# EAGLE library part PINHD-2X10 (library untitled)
PIN HEADER
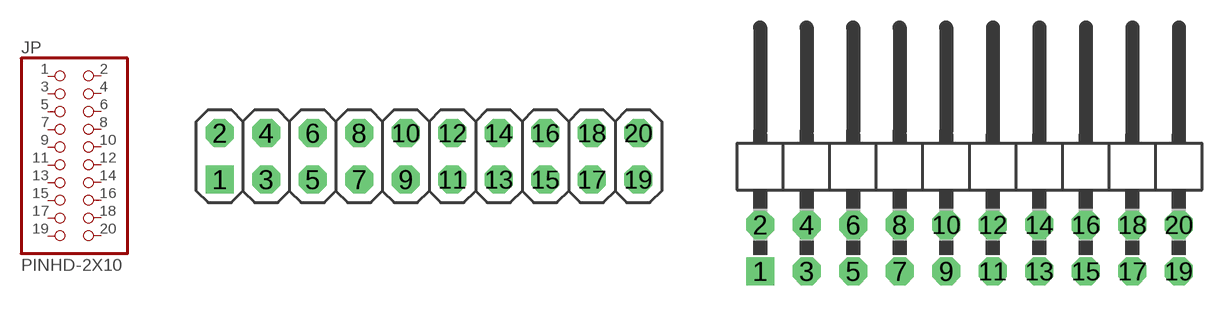
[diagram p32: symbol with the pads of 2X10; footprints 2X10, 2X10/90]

Designator prefix JP

## PINHD-2X10_2.54  [2X10]
1  1  pas
2  2  pas
3  3  pas
4  4  pas
5  5  pas
6  6  pas
7  7  pas
8  8  pas
9  9  pas
10  10  pas
11  11  pas
12  12  pas
13  13  pas
14  14  pas
15  15  pas
16  16  pas
17  17  pas
18  18  pas
19  19  pas
20  20  pas

## PINHD-2X10_2.54-90°  [2X10/90]
Pads as for 2X10

## PINHD-2X10_2.00  [2X10M]
Pads as for 2X10

## PINHD-2X10_2.54-SMD  [2X10SMD]
Pads as for 2X10

## PINHD-2X10_MICROMATCH  [MICROMATCH-20]
Pads as for 2X10

## PINHD-2X10_2.54-SMD-90°  [2X10SMD/90]
Pads as for 2X10

## Footprint 2X10 (pad centres in mm)
PIN HEADER - 2.54
drill 1.016 square: 1 -11.43,-1.27
drill 1.016 octagon: 2 -11.43,1.27; 3 -8.89,-1.27; 4 -8.89,1.27; 5 -6.35,-1.27; 6 -6.35,1.27; 7 -3.81,-1.27; 8 -3.81,1.27; 9 -1.27,-1.27; 10 -1.27,1.27; 11 1.27,-1.27; 12 1.27,1.27; 13 3.81,-1.27; 14 3.81,1.27; 15 6.35,-1.27; 16 6.35,1.27; 17 8.89,-1.27; 18 8.89,1.27; 19 11.43,-1.27; 20 11.43,1.27

## Footprint 2X10/90 (pad centres in mm)
PIN HEADER - 2.54 90°
drill 1.016 square: 1 -11.43,-6.35
drill 1.016 octagon: 2 -11.43,-3.81; 3 -8.89,-6.35; 4 -8.89,-3.81; 5 -6.35,-6.35; 6 -6.35,-3.81; 7 -3.81,-6.35; 8 -3.81,-3.81; 9 -1.27,-6.35; 10 -1.27,-3.81; 11 1.27,-6.35; 12 1.27,-3.81; 13 3.81,-6.35; 14 3.81,-3.81; 15 6.35,-6.35; 16 6.35,-3.81; 17 8.89,-6.35; 18 8.89,-3.81; 19 11.43,-6.35; 20 11.43,-3.81

## Footprint 2X10M (pad centres in mm)
PIN HEADER - 2
drill 0.914 square: 1 -9,-1
drill 0.914 round: 2 -9,1; 3 -7,-1; 4 -7,1; 5 -5,-1; 6 -5,1; 7 -3,-1; 8 -3,1; 9 -1,-1; 10 -1,1; 11 1,-1; 12 1,1; 13 3,-1; 14 3,1; 15 5,-1; 16 5,1; 17 7,-1; 18 7,1; 19 9,-1; 20 9,1

## Footprint 2X10SMD (pad centres in mm)
PIN HEADER - 2.54 SMD
smd 1.016 x 3.302: 1 -1.27,-3.81; 2 -1.27,1.27; 3 1.27,-3.81; 4 1.27,1.27; 5 3.81,-3.81; 6 3.81,1.27; 7 6.35,-3.81; 8 6.35,1.27; 9 8.89,-3.81; 10 8.89,1.27; 11 11.43,-3.81; 12 11.43,1.27; 13 13.97,-3.81; 14 13.97,1.27; 15 16.51,-3.81; 16 16.51,1.27; 17 19.05,-3.81; 18 19.05,1.27; 19 21.59,-3.81; 20 21.59,1.27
